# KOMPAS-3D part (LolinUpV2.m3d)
File: created 12.09.2016 00:20:07, last saved 20.09.2016 00:04:10.
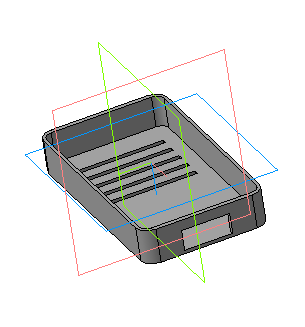
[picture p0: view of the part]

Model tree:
1. Эскиз:1
2. Операция выдавливания:1
     Расстояние 1 = 10
3. Эскиз:2
4. Эскиз:3
5. Вырезать элемент выдавливания:1
     Расстояние 2 = 9; Расстояние 1 = 10
6. Эскиз:4
7. Вырезать элемент выдавливания:2
     Расстояние 2 = 8; Расстояние 1 = 5
8. Эскиз:5
9. Вырезать элемент выдавливания:3
     Расстояние 2 = 8; Расстояние 1 = 10
10. Массив по сетке:1  (with: Вырезать элемент выдавливания:3)  (5 pattern instances)
     Шаг 1 = 5; Угол раствора = 90; Номер 1 = 1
